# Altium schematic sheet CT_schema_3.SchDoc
size 283 x 147 mm
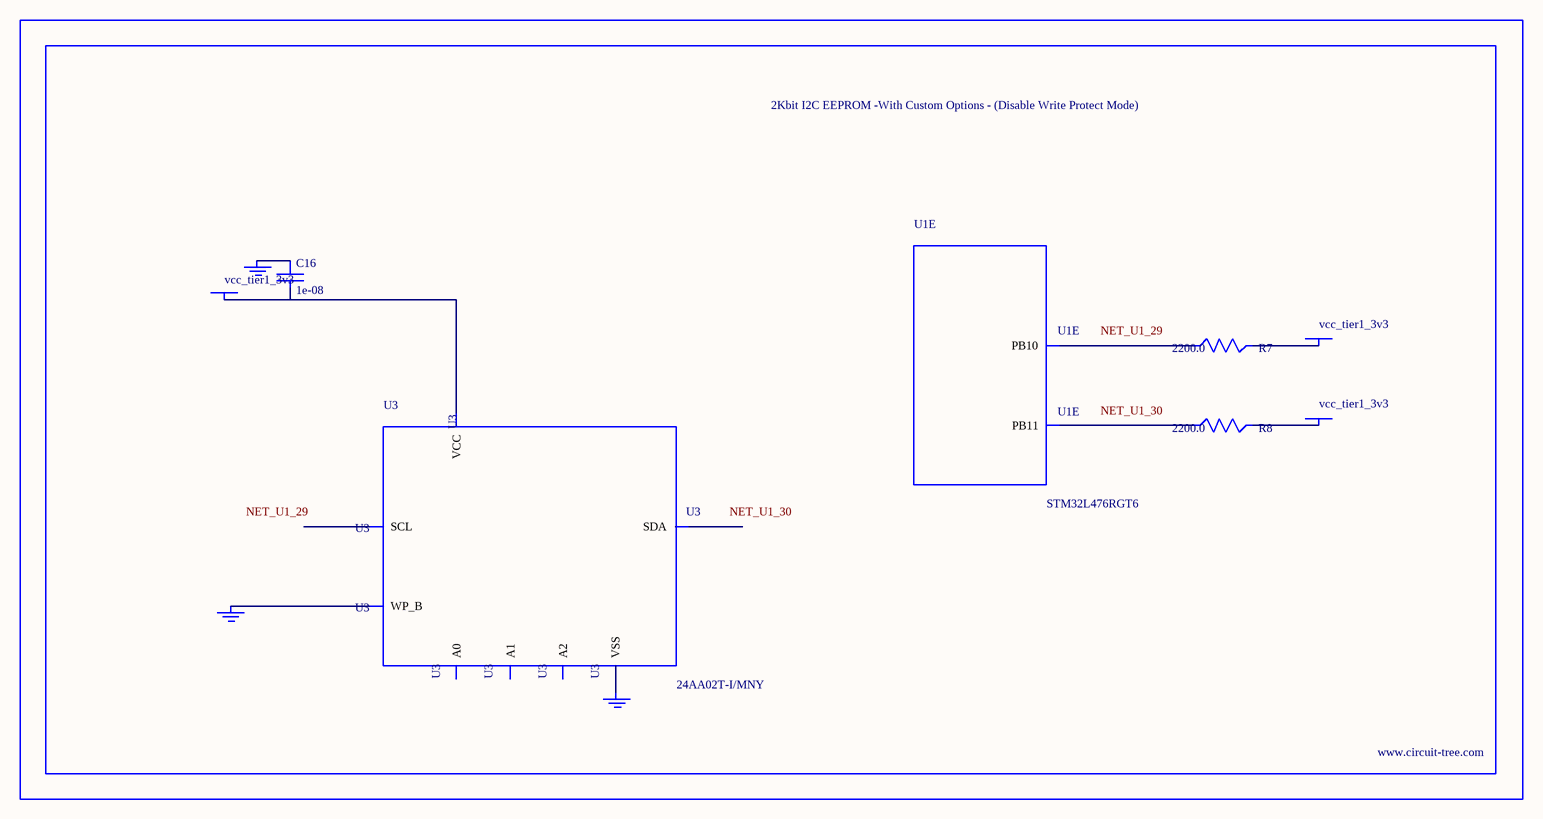
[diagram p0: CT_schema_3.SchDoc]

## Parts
BORDER2  (no value)
C16  1e-08  [C0402]
GND_INSTANCE_2_0  (no value)
GND_INSTANCE_2_1  (no value)
GND_INSTANCE_2_2  (no value)
POWER_INSTANCE_2_0  vcc_tier1_3v3
POWER_INSTANCE_2_1  vcc_tier1_3v3
POWER_INSTANCE_2_2  vcc_tier1_3v3
R7  2200.0  [R0603]
R8  2200.0  [R0603]
U1  STM32L476RGT6  [LQFP64]  (part E of 8)
U3  24AA02T-I/MNY  [TDFN-8/6MM]

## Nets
NetC16_1: C16.1 GND_INSTANCE_2_1.0(GND)
NetC16_2: C16.2 POWER_INSTANCE_2_0.0(PWR) U3.8(VCC)
NetGND_INSTANCE_2_0_0: GND_INSTANCE_2_0.0(GND) U3.7(WP_B)
NetGND_INSTANCE_2_2_0: GND_INSTANCE_2_2.0(GND) U3.4(VSS)
NetPOWER_INSTANCE_2_1_0: POWER_INSTANCE_2_1.0(PWR) R7.2
NetPOWER_INSTANCE_2_2_0: POWER_INSTANCE_2_2.0(PWR) R8.2
NetR7_1: R7.1 U1.29(PB10)
NetR8_1: R8.1 U1.30(PB11)

Not connected (* = marked no-connect by the designer): U3 1(A0) 2(A1) 3(A2) 5(SDA) 6(SCL)

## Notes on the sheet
- Labels drawn without touching a wire or pin: NET_U1_29, NET_U1_30

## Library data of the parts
BORDER2 = BORDER_PAGE2
C16 = C0402C103K3RAC
GND_INSTANCE_2_0-GND_INSTANCE_2_2 = GND
POWER_INSTANCE_2_0-POWER_INSTANCE_2_2 = PWR
R7 R8 = RC0603JR-072K2L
